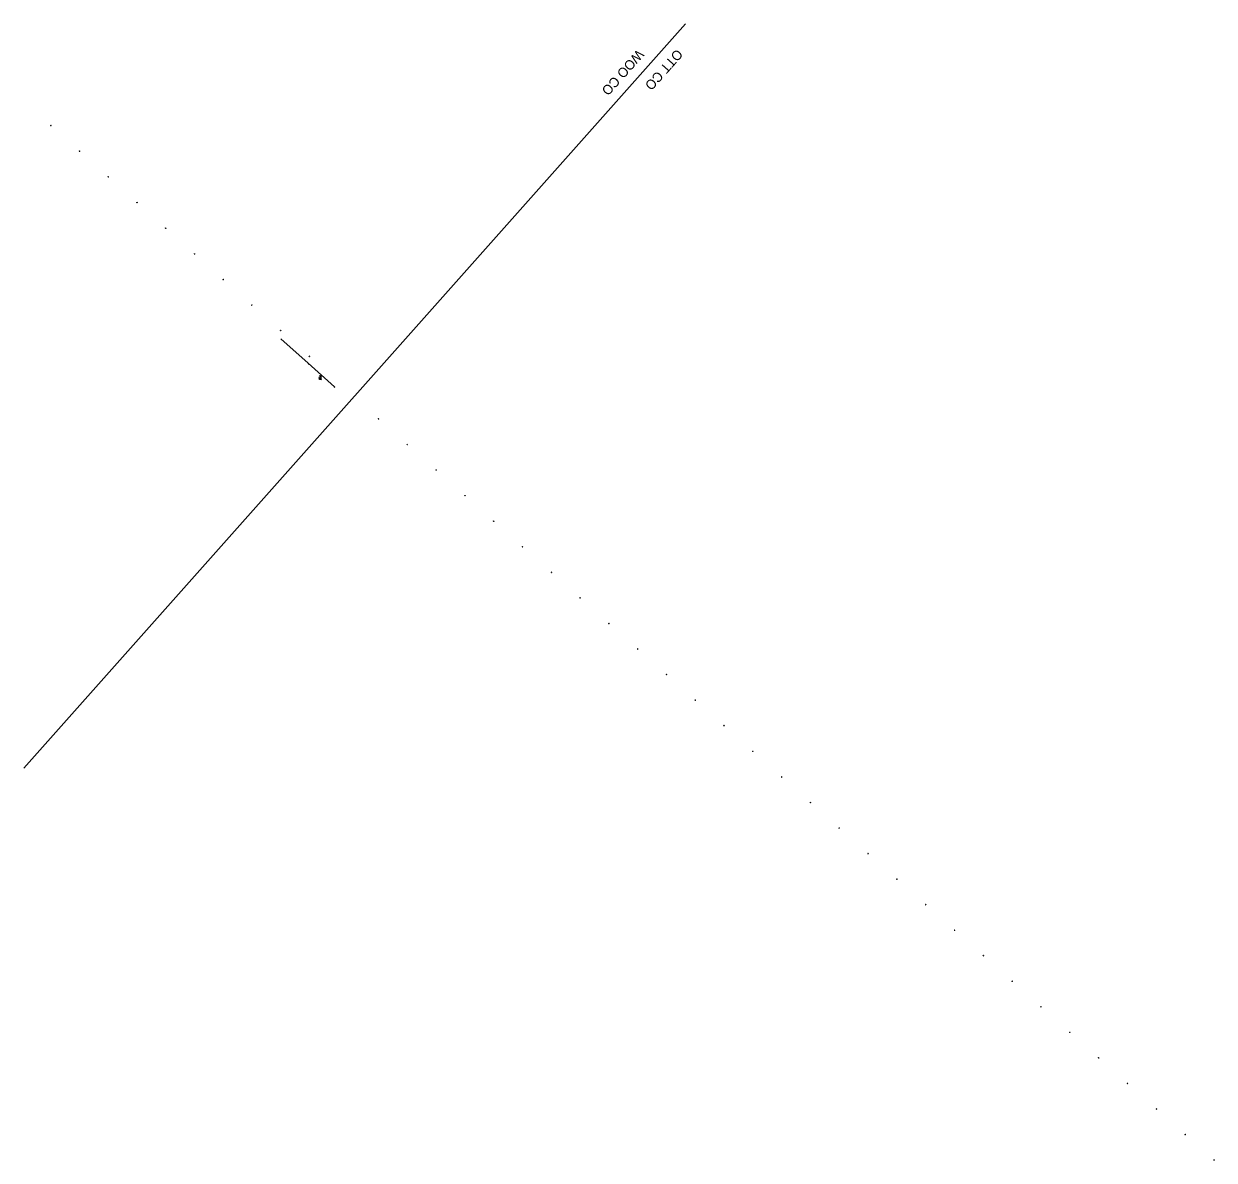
# Model space of a CAD drawing. Extents: x 0 to 963357, y 0 to 528961.
# Drawn here: x 227587 to 230059, y 515414 to 517776 of the extents above; entities that cross this region are included whole.
import ezdxf

# ---------------------------------------------------------------- set-up
doc = ezdxf.new("R2010")
doc.units = 0
for name, color, linetype in [('RW_X_CL_100_Distances', 7, 'Continuous'), ('RW_X_CL_100_Stations', 7, 'Continuous'), ('SC_Scratch2', 7, 'Continuous'), ('SC_Scratch9', 7, 'Continuous')]:
    doc.layers.add(name, color=color, linetype=linetype)

msp = doc.modelspace()

# ---------------------------------------------------------------- linework, layer by layer
at = {"layer": 'RW_X_CL_100_Distances'}
msp.add_line((228177.8, 517070.4), (228120.8, 517121.4), dxfattribs=at)
at = {"layer": 'RW_X_CL_100_Stations'}
msp.add_line((228232.6, 517021.4), (228177.8, 517070.4), dxfattribs=at)
at = {"layer": 'SC_Scratch2'}
msp.add_line((228961.4, 517775.7), (227587, 516229.1), dxfattribs=at)
at = {"layer": 'SC_Scratch9'}
for p, q in [((227642.6, 517564.3), (227642.9, 517564)), ((227642.6, 517564.3), (227642.9, 517564)), ((227642.9, 517564), (227643.2, 517564.4)), ((227642.9, 517564), (227643.2, 517563.8)), ((227643.2, 517564.4), (227643, 517564.7)), ((227643, 517564.7), (227643.2, 517564.4)), ((227643.2, 517564.4), (227643.5, 517564.2)), ((227702.3, 517511), (227702.6, 517510.8)), ((227702.3, 517511), (227702.6, 517510.8)), ((227702.9, 517511.1), (227702.6, 517511.4)), ((227702.6, 517511.4), (227702.9, 517511.1)), ((227702.6, 517510.8), (227702.9, 517511.1)), ((227702.6, 517510.8), (227702.9, 517510.5)), ((227702.9, 517511.1), (227703.2, 517510.9)), ((227762, 517457.7), (227762.3, 517457.5)), ((227762, 517457.7), (227762.3, 517457.5)), ((227762.6, 517457.8), (227762.3, 517458.1)), ((227762.3, 517458.1), (227762.6, 517457.8)), ((227762.3, 517457.5), (227762.6, 517457.8)), ((227762.3, 517457.5), (227762.5, 517457.2)), ((227762.6, 517457.8), (227762.9, 517457.6)), ((227821.6, 517404.4), (227821.9, 517404.2)), ((227821.6, 517404.4), (227821.9, 517404.2)), ((227821.9, 517404.2), (227822.2, 517404.5)), ((227821.9, 517404.2), (227822.2, 517403.9)), ((227822.2, 517404.5), (227822, 517404.8)), ((227822, 517404.8), (227822.2, 517404.5)), ((227822.2, 517404.5), (227822.5, 517404.3)), ((227881.3, 517351.1), (227881.6, 517350.9)), ((227881.3, 517351.1), (227881.6, 517350.9)), ((227881.9, 517351.2), (227881.6, 517351.5)), ((227881.6, 517351.5), (227881.9, 517351.2)), ((227881.6, 517350.9), (227881.9, 517351.2)), ((227881.6, 517350.9), (227881.9, 517350.6)), ((227881.9, 517351.2), (227882.2, 517351)), ((227941, 517297.8), (227941.3, 517297.6)), ((227941, 517297.8), (227941.3, 517297.6)), ((227941.6, 517298), (227941.3, 517298.2)), ((227941.3, 517298.2), (227941.6, 517298)), ((227941.3, 517297.6), (227941.6, 517298)), ((227941.3, 517297.6), (227941.5, 517297.3)), ((227941.6, 517298), (227941.9, 517297.7)), ((228000.6, 517244.6), (228000.9, 517244.3)), ((228000.6, 517244.6), (228000.9, 517244.3)), ((228000.9, 517244.3), (228001.2, 517244.7)), ((228000.9, 517244.3), (228001.2, 517244)), ((228001.2, 517244.7), (228001, 517244.9)), ((228001, 517244.9), (228001.2, 517244.7)), ((228001.2, 517244.7), (228001.5, 517244.4)), ((228060.3, 517191.3), (228060.6, 517191)), ((228060.3, 517191.3), (228060.6, 517191)), ((228060.9, 517191.4), (228060.6, 517191.6)), ((228060.6, 517191.6), (228060.9, 517191.4)), ((228060.6, 517191), (228060.9, 517191.4)), ((228060.6, 517191), (228060.9, 517190.8)), ((228060.9, 517191.4), (228061.2, 517191.1)), ((228120, 517138), (228120.3, 517137.7)), ((228120, 517138), (228120.3, 517137.7)), ((228120.6, 517138.1), (228120.3, 517138.3)), ((228120.3, 517138.3), (228120.6, 517138.1)), ((228120.3, 517137.7), (228120.6, 517138.1)), ((228120.3, 517137.7), (228120.5, 517137.5)), ((228120.6, 517138.1), (228120.9, 517137.8)), ((228179.6, 517084.7), (228179.9, 517084.4)), ((228179.6, 517084.7), (228179.9, 517084.4)), ((228179.9, 517084.4), (228180.2, 517084.8)), ((228179.9, 517084.4), (228180.2, 517084.2)), ((228180.2, 517084.8), (228180, 517085.1)), ((228180, 517085.1), (228180.2, 517084.8)), ((228180.2, 517084.8), (228180.5, 517084.5)), ((228177.5, 517069.6), (228177.8, 517069.3)), ((228177.5, 517069.6), (228177.8, 517069.3)), ((228177.8, 517069.3), (228178.1, 517069.7)), ((228177.8, 517069.3), (228178.1, 517069.1)), ((228178.1, 517069.7), (228177.9, 517069.9)), ((228177.9, 517069.9), (228178.1, 517069.7)), ((228178.1, 517069.7), (228178.4, 517069.4)), ((228199.6, 517042.4), (228199.6, 517042.4)), ((228201.5, 517036.5), (228200.8, 517040.8)), ((228200.8, 517040.8), (228202.2, 517039.1)), ((228201.2, 517044.1), (228201.9, 517044.8)), ((228202.6, 517042.8), (228201.2, 517044.1)), ((228205.4, 517036.9), (228201.5, 517036.5)), ((228201.9, 517044.8), (228203.7, 517043.1)), ((228202.2, 517039.1), (228202.7, 517039.6)), ((228203.8, 517038.5), (228203.3, 517038)), ((228203.3, 517038), (228205.4, 517036.9)), ((228204.9, 517044.6), (228205.2, 517044.3)), ((228204.9, 517044.6), (228205.2, 517044.3)), ((228205.5, 517044.7), (228205.2, 517045)), ((228205.2, 517045), (228205.5, 517044.7)), ((228205.2, 517044.3), (228205.5, 517044.7)), ((228205.2, 517044.3), (228205.4, 517044.1)), ((228205.4, 517036.9), (228205.4, 517036.9)), ((228205.5, 517044.7), (228205.8, 517044.5)), ((228231.5, 517021.2), (228231.8, 517021)), ((228231.5, 517021.2), (228231.8, 517021)), ((228232.1, 517021.3), (228231.8, 517021.6)), ((228231.8, 517021.6), (228232.1, 517021.3)), ((228231.8, 517021), (228232.1, 517021.3)), ((228231.8, 517021), (228232.1, 517020.7)), ((228232.1, 517021.3), (228232.4, 517021.1)), ((228323.3, 516954.9), (228323.6, 516954.6)), ((228323.3, 516954.9), (228323.6, 516954.6)), ((228323.6, 516954.6), (228323.9, 516955)), ((228323.6, 516954.6), (228323.9, 516954.4)), ((228323.9, 516955), (228323.7, 516955.2)), ((228323.7, 516955.2), (228323.9, 516955)), ((228323.9, 516955), (228324.2, 516954.7)), ((228383.1, 516901.7), (228383.4, 516901.5)), ((228383.1, 516901.7), (228383.4, 516901.5)), ((228383.7, 516901.8), (228383.4, 516902.1)), ((228383.4, 516902.1), (228383.7, 516901.8)), ((228383.4, 516901.5), (228383.7, 516901.8)), ((228383.7, 516901.8), (228384, 516901.6)), ((228383.4, 516901.5), (228383.7, 516901.2)), ((228442.9, 516848.6), (228443.2, 516848.3)), ((228442.9, 516848.6), (228443.2, 516848.3)), ((228443.5, 516848.7), (228443.2, 516849)), ((228443.2, 516849), (228443.5, 516848.7)), ((228443.2, 516848.3), (228443.5, 516848.7)), ((228443.2, 516848.3), (228443.5, 516848.1)), ((228443.5, 516848.7), (228443.8, 516848.5)), ((228502.7, 516795.5), (228503, 516795.2)), ((228502.7, 516795.5), (228503, 516795.2)), ((228503.3, 516795.6), (228503, 516795.8)), ((228503, 516795.8), (228503.3, 516795.6)), ((228503, 516795.2), (228503.3, 516795.6)), ((228503, 516795.2), (228503.3, 516794.9)), ((228503.3, 516795.6), (228503.6, 516795.3)), ((228562.5, 516742.3), (228562.8, 516742.1)), ((228562.5, 516742.3), (228562.8, 516742.1)), ((228563.1, 516742.4), (228562.8, 516742.7)), ((228562.8, 516742.7), (228563.1, 516742.4)), ((228562.8, 516742.1), (228563.1, 516742.4)), ((228562.8, 516742.1), (228563.1, 516741.8)), ((228563.1, 516742.4), (228563.4, 516742.2)), ((228622.3, 516689.2), (228622.6, 516688.9)), ((228622.3, 516689.2), (228622.6, 516688.9)), ((228622.9, 516689.3), (228622.6, 516689.5)), ((228622.6, 516689.5), (228622.9, 516689.3)), ((228622.6, 516688.9), (228622.9, 516689.3)), ((228622.6, 516688.9), (228622.9, 516688.7)), ((228622.9, 516689.3), (228623.2, 516689)), ((228682.1, 516636), (228682.4, 516635.8)), ((228682.1, 516636), (228682.4, 516635.8)), ((228682.7, 516636.1), (228682.4, 516636.4)), ((228682.4, 516636.4), (228682.7, 516636.1)), ((228682.4, 516635.8), (228682.7, 516636.1)), ((228682.4, 516635.8), (228682.7, 516635.5)), ((228682.7, 516636.1), (228683, 516635.9)), ((228741.9, 516582.9), (228742.2, 516582.6)), ((228741.9, 516582.9), (228742.2, 516582.6)), ((228742.5, 516583), (228742.2, 516583.2)), ((228742.2, 516583.2), (228742.5, 516583)), ((228742.2, 516582.6), (228742.5, 516583)), ((228742.2, 516582.6), (228742.5, 516582.4)), ((228742.5, 516583), (228742.8, 516582.7)), ((228801.7, 516529.7), (228802, 516529.5)), ((228801.7, 516529.7), (228802, 516529.5)), ((228802.3, 516529.9), (228802, 516530.1)), ((228802, 516530.1), (228802.3, 516529.9)), ((228802, 516529.5), (228802.3, 516529.9)), ((228802, 516529.5), (228802.3, 516529.2)), ((228802.3, 516529.9), (228802.6, 516529.6)), ((228861.5, 516476.6), (228861.8, 516476.3)), ((228861.5, 516476.6), (228861.8, 516476.3)), ((228862.1, 516476.7), (228861.8, 516477)), ((228861.8, 516477), (228862.1, 516476.7)), ((228861.8, 516476.3), (228862.1, 516476.7)), ((228861.8, 516476.3), (228862.1, 516476.1)), ((228862.1, 516476.7), (228862.4, 516476.5)), ((228921.3, 516423.5), (228921.6, 516423.2)), ((228921.3, 516423.5), (228921.6, 516423.2)), ((228921.9, 516423.6), (228921.6, 516423.8)), ((228921.6, 516423.8), (228921.9, 516423.6)), ((228921.6, 516423.2), (228921.9, 516423.6)), ((228921.6, 516423.2), (228921.9, 516422.9)), ((228921.9, 516423.6), (228922.2, 516423.3)), ((228981.1, 516370.3), (228981.4, 516370.1)), ((228981.1, 516370.3), (228981.4, 516370.1)), ((228981.7, 516370.4), (228981.4, 516370.7)), ((228981.4, 516370.7), (228981.7, 516370.4)), ((228981.4, 516370.1), (228981.7, 516370.4)), ((228981.4, 516370.1), (228981.7, 516369.8)), ((228981.7, 516370.4), (228982, 516370.2)), ((229040.9, 516317.2), (229041.2, 516316.9)), ((229040.9, 516317.2), (229041.2, 516316.9)), ((229041.5, 516317.3), (229041.2, 516317.5)), ((229041.2, 516317.5), (229041.5, 516317.3)), ((229041.2, 516316.9), (229041.5, 516317.3)), ((229041.2, 516316.9), (229041.5, 516316.7)), ((229041.5, 516317.3), (229041.8, 516317)), ((229100.7, 516264), (229101, 516263.8)), ((229100.7, 516264), (229101, 516263.8)), ((229101.3, 516264.1), (229101, 516264.4)), ((229101, 516264.4), (229101.3, 516264.1)), ((229101, 516263.8), (229101.3, 516264.1)), ((229101, 516263.8), (229101.3, 516263.5)), ((229101.3, 516264.1), (229101.6, 516263.9)), ((229160.5, 516210.9), (229160.8, 516210.6)), ((229160.5, 516210.9), (229160.8, 516210.6)), ((229161.1, 516211), (229160.8, 516211.2)), ((229160.8, 516211.2), (229161.1, 516211)), ((229160.8, 516210.6), (229161.1, 516211)), ((229160.8, 516210.6), (229161.1, 516210.4)), ((229161.1, 516211), (229161.4, 516210.7)), ((229220.3, 516157.7), (229220.6, 516157.5)), ((229220.3, 516157.7), (229220.6, 516157.5)), ((229220.9, 516157.9), (229220.6, 516158.1)), ((229220.6, 516158.1), (229220.9, 516157.9)), ((229220.6, 516157.5), (229220.9, 516157.9)), ((229220.6, 516157.5), (229220.9, 516157.2)), ((229220.9, 516157.9), (229221.2, 516157.6)), ((229280.1, 516104.6), (229280.4, 516104.3)), ((229280.1, 516104.6), (229280.4, 516104.3)), ((229280.7, 516104.7), (229280.4, 516105)), ((229280.4, 516105), (229280.7, 516104.7)), ((229280.4, 516104.3), (229280.7, 516104.7)), ((229280.4, 516104.3), (229280.7, 516104.1)), ((229280.7, 516104.7), (229281, 516104.5)), ((229339.9, 516051.5), (229340.2, 516051.2)), ((229339.9, 516051.5), (229340.2, 516051.2)), ((229340.2, 516051.2), (229340.6, 516051.6)), ((229340.2, 516051.2), (229340.5, 516051)), ((229340.6, 516051.6), (229340.3, 516051.9)), ((229340.3, 516051.9), (229340.6, 516051.6)), ((229340.6, 516051.6), (229340.8, 516051.3)), ((229399.8, 515998.4), (229400.1, 515998.2)), ((229399.8, 515998.4), (229400.1, 515998.2)), ((229400.4, 515998.5), (229400.1, 515998.8)), ((229400.1, 515998.8), (229400.4, 515998.5)), ((229400.1, 515998.2), (229400.4, 515998.5)), ((229400.1, 515998.2), (229400.4, 515997.9)), ((229400.4, 515998.5), (229400.7, 515998.3)), ((229459.7, 515945.4), (229460, 515945.1)), ((229459.7, 515945.4), (229460, 515945.1)), ((229460.3, 515945.5), (229460, 515945.8)), ((229460, 515945.8), (229460.3, 515945.5)), ((229460, 515945.1), (229460.3, 515945.5)), ((229460, 515945.1), (229460.3, 515944.9)), ((229460.3, 515945.5), (229460.6, 515945.2)), ((229519.6, 515892.3), (229519.9, 515892.1)), ((229519.6, 515892.3), (229519.9, 515892.1)), ((229520.2, 515892.4), (229519.9, 515892.7)), ((229519.9, 515892.7), (229520.2, 515892.4)), ((229519.9, 515892.1), (229520.2, 515892.4)), ((229519.9, 515892.1), (229520.2, 515891.8)), ((229520.2, 515892.4), (229520.5, 515892.2)), ((229579.5, 515839.3), (229579.8, 515839)), ((229579.5, 515839.3), (229579.8, 515839)), ((229580.1, 515839.4), (229579.8, 515839.7)), ((229579.8, 515839.7), (229580.1, 515839.4)), ((229579.8, 515839), (229580.1, 515839.4)), ((229579.8, 515839), (229580, 515838.8)), ((229580.1, 515839.4), (229580.4, 515839.1)), ((229639.3, 515786.2), (229639.6, 515786)), ((229639.3, 515786.2), (229639.6, 515786)), ((229639.6, 515786), (229640, 515786.3)), ((229639.6, 515786), (229639.9, 515785.7)), ((229640, 515786.3), (229639.7, 515786.6)), ((229639.7, 515786.6), (229640, 515786.3)), ((229640, 515786.3), (229640.2, 515786.1)), ((229699.2, 515733.2), (229699.5, 515732.9)), ((229699.2, 515733.2), (229699.5, 515732.9)), ((229699.8, 515733.3), (229699.5, 515733.5)), ((229699.5, 515733.5), (229699.8, 515733.3)), ((229699.5, 515732.9), (229699.8, 515733.3)), ((229699.5, 515732.9), (229699.8, 515732.7)), ((229699.8, 515733.3), (229700.1, 515733)), ((229759.1, 515680.1), (229759.4, 515679.9)), ((229759.1, 515680.1), (229759.4, 515679.9)), ((229759.7, 515680.2), (229759.4, 515680.5)), ((229759.4, 515680.5), (229759.7, 515680.2)), ((229759.4, 515679.9), (229759.7, 515680.2)), ((229759.4, 515679.9), (229759.7, 515679.6)), ((229759.7, 515680.2), (229760, 515680)), ((229819, 515627.1), (229819.3, 515626.8)), ((229819, 515627.1), (229819.3, 515626.8)), ((229819.6, 515627.2), (229819.3, 515627.4)), ((229819.3, 515627.4), (229819.6, 515627.2)), ((229819.3, 515626.8), (229819.6, 515627.2)), ((229819.3, 515626.8), (229819.6, 515626.6)), ((229819.6, 515627.2), (229819.9, 515626.9)), ((229878.9, 515574), (229879.2, 515573.8)), ((229878.9, 515574), (229879.2, 515573.8)), ((229879.5, 515574.1), (229879.2, 515574.4)), ((229879.2, 515574.4), (229879.5, 515574.1)), ((229879.2, 515573.8), (229879.5, 515574.1)), ((229879.2, 515573.8), (229879.4, 515573.5)), ((229879.5, 515574.1), (229879.8, 515573.9)), ((229938.7, 515521), (229939, 515520.7)), ((229938.7, 515521), (229939, 515520.7)), ((229939, 515520.7), (229939.4, 515521.1)), ((229939, 515520.7), (229939.3, 515520.5)), ((229939.4, 515521.1), (229939.1, 515521.3)), ((229939.1, 515521.3), (229939.4, 515521.1)), ((229939.4, 515521.1), (229939.6, 515520.8)), ((229998.6, 515467.9), (229998.9, 515467.7)), ((229998.6, 515467.9), (229998.9, 515467.7)), ((229999.2, 515468), (229998.9, 515468.3)), ((229998.9, 515468.3), (229999.2, 515468)), ((229998.9, 515467.7), (229999.2, 515468)), ((229999.2, 515468), (229999.5, 515467.8)), ((229998.9, 515467.7), (229999.2, 515467.4)), ((230058.5, 515414.9), (230058.8, 515414.6)), ((230058.5, 515414.9), (230058.8, 515414.6)), ((230059.1, 515415), (230058.8, 515415.2)), ((230058.8, 515415.2), (230059.1, 515415)), ((230058.8, 515414.6), (230059.1, 515415)), ((230058.8, 515414.6), (230059.1, 515414.4)), ((230059.1, 515415), (230059.4, 515414.7))]:
    msp.add_line(p, q, dxfattribs=at)
for centre, radius, start, end in [((227642.7, 517564.6), 0.288, 260.2046, 16.2569), ((227642.7, 517564.6), 0.288, 260.2046, 16.2569), ((227643.5, 517563.9), 0.288, 80.2046, 196.2569), ((227702.3, 517511.3), 0.288, 260.2046, 16.2569), ((227702.3, 517511.3), 0.288, 260.2046, 16.2569), ((227703.1, 517510.6), 0.288, 80.2046, 196.2569), ((227762, 517458), 0.288, 260.2046, 16.2569), ((227762, 517458), 0.288, 260.2046, 16.2569), ((227762.8, 517457.3), 0.288, 80.2046, 196.2569), ((227821.7, 517404.7), 0.288, 260.2046, 16.2569), ((227821.7, 517404.7), 0.288, 260.2046, 16.2569), ((227822.5, 517404), 0.288, 80.2046, 196.2569), ((227881.3, 517351.4), 0.288, 260.2046, 16.2569), ((227881.3, 517351.4), 0.288, 260.2046, 16.2569), ((227882.1, 517350.7), 0.288, 80.2046, 196.2569), ((227941, 517298.1), 0.288, 260.2046, 16.2569), ((227941, 517298.1), 0.288, 260.2046, 16.2569), ((227941.8, 517297.4), 0.288, 80.2046, 196.2569), ((228000.7, 517244.8), 0.288, 260.2046, 16.2569), ((228000.7, 517244.8), 0.288, 260.2046, 16.2569), ((228001.5, 517244.1), 0.288, 80.2046, 196.2569), ((228060.3, 517191.6), 0.288, 260.2046, 16.2569), ((228060.3, 517191.6), 0.288, 260.2046, 16.2569), ((228061.1, 517190.8), 0.288, 80.2046, 196.2569), ((228120, 517138.3), 0.288, 260.2046, 16.2569), ((228120, 517138.3), 0.288, 260.2046, 16.2569), ((228120.8, 517137.5), 0.288, 80.2046, 196.2569), ((228179.7, 517085), 0.288, 260.2046, 16.2569), ((228179.7, 517085), 0.288, 260.2046, 16.2569), ((228180.5, 517084.3), 0.288, 80.2046, 196.2569), ((228177.6, 517069.9), 0.288, 260.7256, 16.7779), ((228177.6, 517069.9), 0.288, 260.7256, 16.7779), ((228178.4, 517069.1), 0.288, 80.7256, 196.7779), ((228201, 517041.1), 2.3, 316.7001, 46.7001), ((228201.4, 517040.7), 3.28, 315.7916, 46.7001), ((228204.9, 517044.9), 0.288, 260.7256, 16.7779), ((228204.9, 517044.9), 0.288, 260.7256, 16.7779), ((228205.7, 517044.2), 0.288, 80.7256, 196.7779), ((228231.6, 517021.5), 0.288, 260.7256, 16.7779), ((228231.6, 517021.5), 0.288, 260.7256, 16.7779), ((228232.4, 517020.8), 0.288, 80.7256, 196.7779), ((228323.4, 516955.2), 0.288, 260.647, 16.6994), ((228323.4, 516955.2), 0.288, 260.647, 16.6994), ((228324.2, 516954.5), 0.288, 80.647, 196.6994), ((228383.2, 516902), 0.288, 260.647, 16.6994), ((228383.2, 516902), 0.288, 260.647, 16.6994), ((228384, 516901.3), 0.288, 80.647, 196.6994), ((228443, 516848.9), 0.288, 260.647, 16.6994), ((228443, 516848.9), 0.288, 260.647, 16.6994), ((228443.8, 516848.2), 0.288, 80.647, 196.6994), ((228502.8, 516795.7), 0.288, 260.647, 16.6994), ((228502.8, 516795.7), 0.288, 260.647, 16.6994), ((228503.6, 516795), 0.288, 80.647, 196.6994), ((228562.6, 516742.6), 0.288, 260.647, 16.6994), ((228562.6, 516742.6), 0.288, 260.647, 16.6994), ((228563.4, 516741.9), 0.288, 80.647, 196.6994), ((228622.4, 516689.4), 0.288, 260.647, 16.6994), ((228622.4, 516689.4), 0.288, 260.647, 16.6994), ((228623.2, 516688.7), 0.288, 80.647, 196.6994), ((228682.2, 516636.3), 0.288, 260.647, 16.6994), ((228682.2, 516636.3), 0.288, 260.647, 16.6994), ((228683, 516635.6), 0.288, 80.647, 196.6994), ((228742, 516583.2), 0.288, 260.647, 16.6994), ((228742, 516583.2), 0.288, 260.647, 16.6994), ((228742.8, 516582.5), 0.288, 80.647, 196.6994), ((228801.8, 516530), 0.288, 260.647, 16.6994), ((228801.8, 516530), 0.288, 260.647, 16.6994), ((228802.6, 516529.3), 0.288, 80.647, 196.6994), ((228861.6, 516476.9), 0.288, 260.647, 16.6994), ((228861.6, 516476.9), 0.288, 260.647, 16.6994), ((228862.4, 516476.2), 0.288, 80.647, 196.6994), ((228921.4, 516423.7), 0.288, 260.647, 16.6994), ((228921.4, 516423.7), 0.288, 260.647, 16.6994), ((228922.2, 516423), 0.288, 80.647, 196.6994), ((228981.2, 516370.6), 0.288, 260.647, 16.6994), ((228981.2, 516370.6), 0.288, 260.647, 16.6994), ((228982, 516369.9), 0.288, 80.647, 196.6994), ((229041, 516317.5), 0.288, 260.647, 16.6994), ((229041, 516317.5), 0.288, 260.647, 16.6994), ((229041.8, 516316.7), 0.288, 80.647, 196.6994), ((229100.8, 516264.3), 0.288, 260.647, 16.6994), ((229100.8, 516264.3), 0.288, 260.647, 16.6994), ((229101.6, 516263.6), 0.288, 80.647, 196.6994), ((229160.6, 516211.2), 0.288, 260.647, 16.6994), ((229160.6, 516211.2), 0.288, 260.647, 16.6994), ((229161.4, 516210.5), 0.288, 80.647, 196.6994), ((229220.4, 516158), 0.288, 260.647, 16.6994), ((229220.4, 516158), 0.288, 260.647, 16.6994), ((229221.2, 516157.3), 0.288, 80.647, 196.6994), ((229280.2, 516104.9), 0.288, 260.647, 16.6994), ((229280.2, 516104.9), 0.288, 260.647, 16.6994), ((229281, 516104.2), 0.288, 80.647, 196.6994), ((229340, 516051.8), 0.288, 260.7352, 16.7875), ((229340, 516051.8), 0.288, 260.7352, 16.7875), ((229340.8, 516051.1), 0.288, 80.7352, 196.7875), ((229399.9, 515998.7), 0.288, 260.7352, 16.7875), ((229399.9, 515998.7), 0.288, 260.7352, 16.7875), ((229400.7, 515998), 0.288, 80.7352, 196.7875), ((229459.7, 515945.7), 0.288, 260.7352, 16.7875), ((229459.7, 515945.7), 0.288, 260.7352, 16.7875), ((229460.6, 515945), 0.288, 80.7352, 196.7875), ((229519.6, 515892.6), 0.288, 260.7352, 16.7875), ((229519.6, 515892.6), 0.288, 260.7352, 16.7875), ((229520.4, 515891.9), 0.288, 80.7352, 196.7875), ((229579.5, 515839.6), 0.288, 260.7352, 16.7875), ((229579.5, 515839.6), 0.288, 260.7352, 16.7875), ((229580.3, 515838.9), 0.288, 80.7352, 196.7875), ((229639.4, 515786.5), 0.288, 260.7352, 16.7875), ((229639.4, 515786.5), 0.288, 260.7352, 16.7875), ((229640.2, 515785.8), 0.288, 80.7352, 196.7875), ((229699.3, 515733.5), 0.288, 260.7352, 16.7875), ((229699.3, 515733.5), 0.288, 260.7352, 16.7875), ((229700.1, 515732.8), 0.288, 80.7352, 196.7875), ((229759.1, 515680.4), 0.288, 260.7352, 16.7875), ((229759.1, 515680.4), 0.288, 260.7352, 16.7875), ((229760, 515679.7), 0.288, 80.7352, 196.7875), ((229819, 515627.4), 0.288, 260.7352, 16.7875), ((229819, 515627.4), 0.288, 260.7352, 16.7875), ((229819.8, 515626.7), 0.288, 80.7352, 196.7875), ((229878.9, 515574.3), 0.288, 260.7352, 16.7875), ((229878.9, 515574.3), 0.288, 260.7352, 16.7875), ((229879.7, 515573.6), 0.288, 80.7352, 196.7875), ((229938.8, 515521.3), 0.288, 260.7352, 16.7875), ((229938.8, 515521.3), 0.288, 260.7352, 16.7875), ((229939.6, 515520.6), 0.288, 80.7352, 196.7875), ((229998.7, 515468.2), 0.288, 260.7352, 16.7875), ((229998.7, 515468.2), 0.288, 260.7352, 16.7875), ((229999.5, 515467.5), 0.288, 80.7352, 196.7875), ((230058.6, 515415.2), 0.288, 260.7352, 16.7875), ((230058.6, 515415.2), 0.288, 260.7352, 16.7875), ((230059.4, 515414.5), 0.288, 80.7352, 196.7875)]:
    msp.add_arc(centre, radius, start, end, dxfattribs=at)

# ---------------------------------------------------------------- texts
at = {"layer": 'SC_Scratch2'}
for s, p in [('WOO CO', (228861.7, 517723.7)), ('OTT CO', (228942.7, 517724.5))]:
    msp.add_text(s, height=20, rotation=228.3728, dxfattribs=at).set_placement(p)

doc.saveas('drawing.dxf')
